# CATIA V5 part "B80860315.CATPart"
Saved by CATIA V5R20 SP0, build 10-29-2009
Part number: B80860315
Revision: 2
Definition: design
Nomenclature: B80860315
Source: made
Description: NOT SPECIFIED
Bounding box of the stored display mesh (mm): x -32.322 to 32.322, y -32.5 to 32.5, z 0 to 315
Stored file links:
  C:\Users\Raffaele\Desktop\3D X SITO CF\BOLEX\4-PILLAR REF 808\B80860315.CATPart
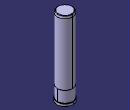
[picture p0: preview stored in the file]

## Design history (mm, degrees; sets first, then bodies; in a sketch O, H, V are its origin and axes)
Body1 "MANIFOLD_SOLID_BREP #450" (main body)
  Solid1: solid without history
